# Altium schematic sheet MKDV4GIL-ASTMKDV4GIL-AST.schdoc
size 127 x 101 mm
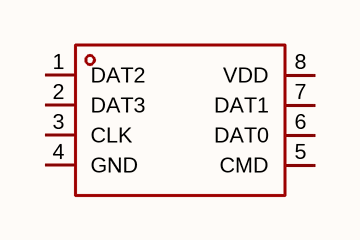
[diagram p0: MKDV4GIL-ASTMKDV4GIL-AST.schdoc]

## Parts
U?  mkdv4gil-ast  [LGA-8_L8.0-W6.0-TL_MKDV4GIL-AS]  (value not drawn)

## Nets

Not connected (* = marked no-connect by the designer): U? 1(DAT2) 2(DAT3) 3(CLK) 4(GND) 5(CMD) 6(DAT0) 7(DAT1) 8(VDD)

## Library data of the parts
U? = mkdv4gil-ast: 存储容量:4Gbit;时钟频率(fc):50MHz;工作电压:2.7V~3.6V;; Manufacturer: MK(米客方德); AddInBom: yes; ModelId: 2a3ea4d1f9da4240ad6f4a8a0d5a5dde; ModelName: LGA-8_L8.0-W6.0-H0.8-P1.27-TL_ MKDV4GIL-AS; ModelTransform: 314.96,236.22,0,0,0,0,0,0,0; Memory Size: 4Gbit; Clock Frequency: 50MHz; Interface: SD2.0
